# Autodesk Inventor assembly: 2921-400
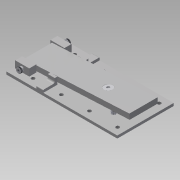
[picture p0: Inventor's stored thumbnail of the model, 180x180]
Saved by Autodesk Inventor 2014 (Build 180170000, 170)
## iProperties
Company: NHTSA/VRTC
Created: 2012-08
Part Number: 2921-400
Project: CHILD SIDE IMPACT SLED
Description: ANTI-REBOUND FIXTURE ASS'Y.
Document SubType Name: Weldment
Designer: Mike Vanvoorhis
Weld Material: Welded Steel Mild
Mass: 12341 g
Surface Area: 3135.86 cm^2
Volume: 1591.33 cm^3
Density: 7.75514 g/cm^3
DESIGN DATE: 2012-11-05
Title: Anti-Rebound Fixture Assembly
Subject: Child Side Impact Sled
Author: Dave Walker
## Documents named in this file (12)
- B:\VRTC_DWG\BIO\Non-P572\Child Side-Frontal Impact Sled\Side Impact Sled\Anti_Rebound_Fixture_Assembly-01.iam
- B:\VRTC_DWG\BIO\Non-P572\Child Side-Frontal Impact Sled\Side Impact Sled\Anti_Rebound_Fixture_Base.ipt
- B:\VRTC_DWG\BIO\Non-P572\Child Side-Frontal Impact Sled\Side Impact Sled\Anti_Rebound_Fixture_Pivot.ipt
- B:\VRTC_DWG\BIO\Non-P572\Child Side-Frontal Impact Sled\Side Impact Sled\Anti_Rebound_Fixture_Stop.ipt
- B:\VRTC_DWG\BIO\Non-P572\Child Side-Frontal Impact Sled\Side Impact Sled\Anti_Rebound_Fixture_Shoulder Bolt.ipt
- B:\VRTC_DWG\BIO\Non-P572\Child Side-Frontal Impact Sled\Side Impact Sled\Anti_Rebound_Fixture_Guide.ipt
- B:\VRTC_DWG\BIO\Non-P572\Child Side-Frontal Impact Sled\Side Impact Sled\Anti_Rebound_Fixture_Spring.ipt
- B:\VRTC_DWG\BIO\Non-P572\Child Side-Frontal Impact Sled\Side Impact Sled\90630A130.ipt
- B:\VRTC_DWG\BIO\Non-P572\Child Side-Frontal Impact Sled\Side Impact Sled\Rubber_Washer.ipt
- B:\VRTC_DWG\BIO\Non-P572\Child Side-Frontal Impact Sled\Side Impact Sled\91253A808.ipt
- B:\VRTC_DWG\Inventor Support Files\Content Center\en-US\ASTM F436(1)\ASTM F436 - 5_8(1).ipt
- B:\VRTC_DWG\BIO\Non-P572\Child Side-Frontal Impact Sled\Side Impact Sled\Anti_Rebound_Fixture_Assembly.iam
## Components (16 placed, 10 different names)
1. Anti_Rebound_Fixture_Base:1 — Flush:1, Flush:2, Flush:3, Flush:4, Mate:1, Flush:5, Flush:6, Flush:8, Insert:9, Flush:10, Flush:11, Flush:12, Insert:20, Insert:22, Insert:23
2. Anti_Rebound_Fixture_Pivot:1 — Flush:1, Insert:12, Insert:13, Flush:10, Flush:12
3. Anti_Rebound_Fixture_Pivot:2 — Flush:2, Flush:3, Mate:2, Flush:9, Flush:11
4. Anti_Rebound_Fixture_Stop:1 — Insert:12, Insert:17, Tangent:1
5. Anti_Rebound_Fixture_Shoulder Bolt:1 — Insert:13
6. Anti_Rebound_Fixture_Shoulder Bolt:2 — Mate:2, Flush:9
7. Anti_Rebound_Fixture_Guide:1 — Flush:4, Mate:1, Flush:7, Flush:8
8. Anti_Rebound_Fixture_Guide:2 — Flush:5, Flush:6, Flush:7
9. Anti_Rebound_Fixture_Spring:1 — Insert:22, Tangent:1
10. Anti_Rebound_Fixture_Spring:2 — Insert:9
11. Anti_Rebound_Fixture_Spring:3 — Insert:23
12. Anti_Rebound_Fixture_Spring:5 — Insert:20
13. 90630A130:1 — Insert:16, Insert:18
14. Rubber_Washer:1 — Insert:19
15. Socket Flat Countersunk Head Cap Screw - Inch 5/8-11 UNC x 3.5 — Insert:16, Insert:17
16. Circular Washer (Inch) 5/8:1 — Insert:18, Insert:19
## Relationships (25: Flush 12, Insert 10, Mate 2, Tangent 1)
- Flush:1: Anti_Rebound_Fixture_Base:1 ↔ Anti_Rebound_Fixture_Pivot:1
- Flush:2: Anti_Rebound_Fixture_Base:1 ↔ Anti_Rebound_Fixture_Pivot:2
- Flush:3: Anti_Rebound_Fixture_Base:1 ↔ Anti_Rebound_Fixture_Pivot:2
- Flush:4: Anti_Rebound_Fixture_Base:1 ↔ Anti_Rebound_Fixture_Guide:1
- Mate:1: Anti_Rebound_Fixture_Base:1 ↔ Anti_Rebound_Fixture_Guide:1
- Flush:5: Anti_Rebound_Fixture_Base:1 ↔ Anti_Rebound_Fixture_Guide:2
- Flush:6: Anti_Rebound_Fixture_Base:1 ↔ Anti_Rebound_Fixture_Guide:2
- Flush:7: Anti_Rebound_Fixture_Guide:1 ↔ Anti_Rebound_Fixture_Guide:2
- Flush:8: Anti_Rebound_Fixture_Base:1 ↔ Anti_Rebound_Fixture_Guide:1
- Insert:9: Anti_Rebound_Fixture_Base:1 ↔ Anti_Rebound_Fixture_Spring:2
- Insert:12: Anti_Rebound_Fixture_Pivot:1 ↔ Anti_Rebound_Fixture_Stop:1
- Insert:13: Anti_Rebound_Fixture_Pivot:1 ↔ Anti_Rebound_Fixture_Shoulder Bolt:1
- Mate:2: Anti_Rebound_Fixture_Pivot:2 ↔ Anti_Rebound_Fixture_Shoulder Bolt:2
- Flush:9: Anti_Rebound_Fixture_Pivot:2 ↔ Anti_Rebound_Fixture_Shoulder Bolt:2
- Flush:10: Anti_Rebound_Fixture_Base:1 ↔ Anti_Rebound_Fixture_Pivot:1
- Flush:11: Anti_Rebound_Fixture_Base:1 ↔ Anti_Rebound_Fixture_Pivot:2
- Flush:12: Anti_Rebound_Fixture_Base:1 ↔ Anti_Rebound_Fixture_Pivot:1
- Insert:16: 90630A130:1 ↔ Socket Flat Countersunk Head Cap Screw - Inch 5/8-11 UNC x 3.5
- Insert:17: Anti_Rebound_Fixture_Stop:1 ↔ Socket Flat Countersunk Head Cap Screw - Inch 5/8-11 UNC x 3.5
- Insert:18: 90630A130:1 ↔ Circular Washer (Inch) 5/8:1
- Insert:19: Rubber_Washer:1 ↔ Circular Washer (Inch) 5/8:1
- Insert:20: Anti_Rebound_Fixture_Base:1 ↔ Anti_Rebound_Fixture_Spring:5
- Insert:22: Anti_Rebound_Fixture_Base:1 ↔ Anti_Rebound_Fixture_Spring:1
- Insert:23: Anti_Rebound_Fixture_Base:1 ↔ Anti_Rebound_Fixture_Spring:3
- Tangent:1: Anti_Rebound_Fixture_Stop:1 ↔ Anti_Rebound_Fixture_Spring:1
